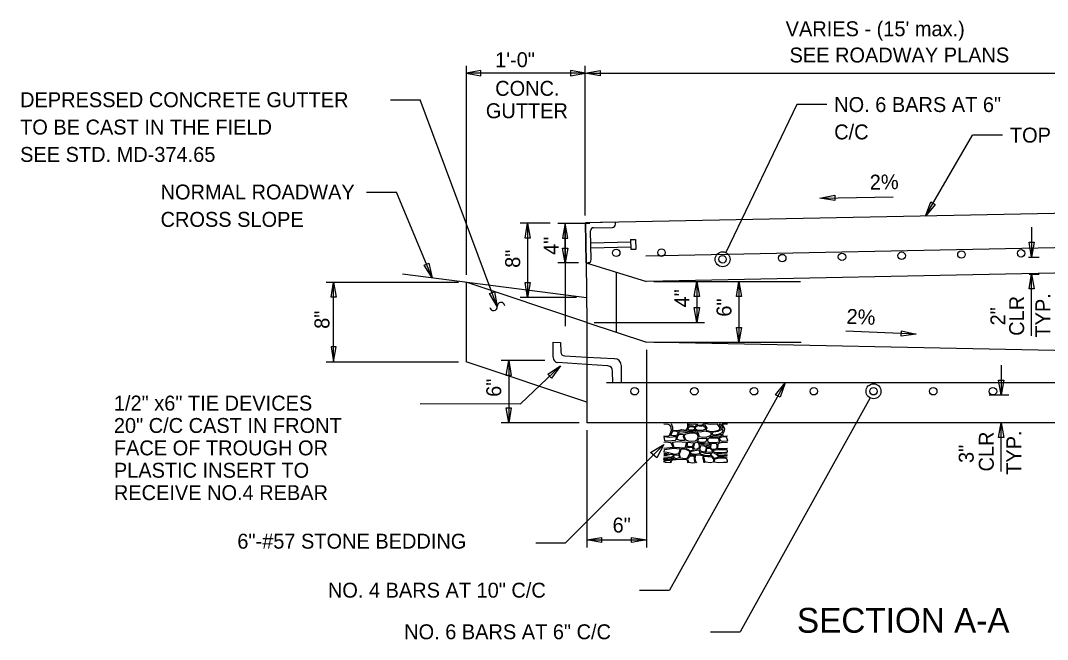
# Model space of a CAD drawing. Extents: x 12.4 to 21.1, y 6 to 16.1.
# Drawn here: x 12.53 to 16.657, y 10.416 to 12.903 of the extents above; entities that cross this region are included whole.
import ezdxf

# ---------------------------------------------------------------- set-up
doc = ezdxf.new("R2010")
doc.units = 0
for name, color, linetype in [('V7_LEVEL_1', 7, 'Continuous'), ('V7_LEVEL_10', 7, 'Continuous'), ('V7_LEVEL_12', 7, 'Continuous')]:
    doc.layers.add(name, color=color, linetype=linetype)

msp = doc.modelspace()

# ---------------------------------------------------------------- linework, layer by layer
at = {"layer": 'V7_LEVEL_1'}
for p, q in [((17.5204, 12.1444), (14.8004, 12.09)), ((14.9204, 12.0924), (14.8004, 12.09)), ((14.9205, 12.0844), (14.9204, 12.0924)), ((14.8036, 11.93), (14.8004, 12.09)), ((14.8004, 12.09), (14.8036, 11.93)), ((14.8004, 12.09), (14.8036, 11.93)), ((14.8233, 11.9424), (14.821, 12.0584)), ((14.8328, 12.0706), (14.9088, 12.0721)), ((14.822, 12.0104), (14.982, 12.0136)), ((14.9818, 12.0228), (15.0018, 12.0232)), ((14.9818, 12.0228), (14.9825, 11.9844)), ((15.0018, 12.0232), (15.0025, 11.9848)), ((17.6389, 12.0086), (15.0431, 11.9567)), ((14.8224, 11.9904), (14.9824, 11.9936)), ((14.9825, 11.9844), (15.0025, 11.9848)), ((14.8036, 11.93), (14.8116, 11.9302)), ((14.8036, 11.93), (15.0451, 11.8548)), ((14.8036, 11.93), (14.8052, 11.69)), ((14.9252, 11.65), (14.9251, 11.8922)), ((17.6852, 11.9076), (15.0451, 11.8548)), ((14.8048, 11.7894), (14.0655, 11.8839)), ((14.8052, 11.69), (14.3204, 11.8516)), ((14.3204, 11.8516), (14.3204, 11.5316)), ((14.8052, 11.69), (14.8052, 11.2868)), ((14.8052, 11.69), (15.0452, 11.61)), ((14.6699, 11.5507), (14.6705, 11.6112)), ((14.6705, 11.6112), (14.7003, 11.6099)), ((14.7003, 11.6099), (14.7008, 11.5717)), ((17.5252, 11.5604), (15.0452, 11.61)), ((14.7175, 11.5552), (14.8053, 11.5504)), ((14.8052, 11.37), (14.3204, 11.5316)), ((14.8053, 11.5207), (14.6893, 11.5284)), ((14.8053, 11.5504), (14.9161, 11.5444)), ((14.8887, 11.5161), (14.8053, 11.5205)), ((14.9436, 11.5188), (14.9441, 11.447)), ((14.9105, 11.4465), (14.9095, 11.4936)), ((17.3791, 11.4467), (14.8852, 11.4467)), ((14.9441, 11.447), (14.9104, 11.4468)), ((17.2852, 11.2868), (14.8052, 11.2868))]:
    msp.add_line(p, q, dxfattribs=at)
for centre in [(14.9241, 11.9698), (15.1059, 11.9706), (15.8311, 11.9534), (16.071, 11.9582), (16.311, 11.963), (16.5509, 11.9678), (15.3512, 11.9438), (15.5911, 11.9486), (14.9978, 11.4133), (15.2378, 11.4133), (15.4778, 11.4133), (15.7178, 11.4133), (15.9578, 11.4133), (16.1978, 11.4133), (16.4378, 11.4133)]:
    msp.add_circle(centre, 0.015, dxfattribs=at)
for centre, radius, start, end in [((14.833, 12.0586), 0.012, 91.1458, 181.1458), ((14.9085, 12.0841), 0.012, 271.1458, 1.1458), ((14.8113, 11.9422), 0.012, 271.1458, 1.1458), ((14.7174, 11.5718), 0.0166, 180.2549, 269.9363), ((14.6904, 11.5484), 0.02, 177.1964, 266.8777), ((14.8894, 11.4952), 0.02, 356.8804, 86.869), ((14.9182, 11.5189), 0.0251, 2.024, 91.7054)]:
    msp.add_arc(centre, radius, start, end, dxfattribs=at)
at = {"layer": 'V7_LEVEL_10'}
for p, q in [((14.3204, 12.7218), (14.3204, 11.8816)), ((14.7989, 12.12), (14.7989, 12.7218)), ((14.7989, 12.12), (14.7989, 12.7218)), ((14.3804, 12.7023), (14.3204, 12.6918)), ((14.8004, 12.6918), (14.3204, 12.6918)), ((14.3204, 12.6918), (14.3804, 12.6813)), ((14.3804, 12.6813), (14.3804, 12.7023)), ((14.8004, 12.6918), (14.7404, 12.7023)), ((14.7404, 12.7023), (14.7404, 12.6813)), ((14.7404, 12.6813), (14.8004, 12.6918)), ((14.7989, 12.6918), (14.8589, 12.7023)), ((14.7989, 12.6918), (17.5204, 12.6918)), ((14.8589, 12.6813), (14.7989, 12.6918)), ((14.8589, 12.7023), (14.8589, 12.6813)), ((14.0163, 12.5853), (14.1363, 12.5853)), ((14.4461, 11.7537), (14.1363, 12.5853)), ((15.6499, 12.5658), (15.3641, 11.9708)), ((15.7699, 12.5658), (15.6499, 12.5658)), ((16.1664, 12.1173), (16.356, 12.443)), ((16.4759, 12.443), (16.3559, 12.443)), ((13.9211, 12.2141), (14.0411, 12.2141)), ((14.1844, 11.8687), (14.0411, 12.2141)), ((15.7426, 12.1894), (16.0371, 12.1953)), ((14.6579, 12.0892), (14.5379, 12.0892)), ((14.5679, 12.0892), (14.5679, 11.7906)), ((14.689, 12.0892), (14.8173, 12.0892)), ((14.719, 12.0892), (14.7085, 12.0292)), ((14.719, 11.929), (14.719, 12.0892)), ((14.7295, 12.0292), (14.719, 12.0892)), ((14.719, 12.0892), (14.719, 11.6744)), ((16.5933, 12.0728), (16.5933, 11.9528)), ((14.7085, 12.0292), (14.7295, 12.0292)), ((14.719, 11.929), (14.7085, 11.989)), ((14.7085, 11.989), (14.7295, 11.989)), ((14.7295, 11.989), (14.719, 11.929)), ((14.7729, 11.929), (14.689, 11.929)), ((16.5809, 11.9528), (16.6233, 11.9528)), ((13.7584, 11.8516), (14.2904, 11.8516)), ((13.7779, 11.7916), (13.7884, 11.8516)), ((13.7884, 11.5316), (13.7884, 11.8516)), ((13.7884, 11.8516), (13.7989, 11.7916)), ((15.0751, 11.8548), (15.278, 11.8548)), ((15.0751, 11.8548), (15.6647, 11.8548)), ((15.248, 11.8548), (15.248, 11.69)), ((15.4172, 11.8548), (15.4172, 11.61)), ((16.5836, 11.8844), (16.6233, 11.8844)), ((16.5933, 11.6361), (16.5933, 11.8844)), ((13.7989, 11.7916), (13.7779, 11.7916)), ((14.7646, 11.7906), (14.5379, 11.7906)), ((14.8352, 11.69), (15.278, 11.69)), ((16.1292, 11.6432), (15.8472, 11.6548)), ((15.0752, 11.61), (15.6667, 11.61)), ((13.7989, 11.5916), (13.7779, 11.5916)), ((13.7779, 11.5916), (13.7884, 11.5316)), ((13.7884, 11.5316), (13.7989, 11.5916)), ((15.0452, 11.58), (15.0452, 10.7854)), ((13.7584, 11.5316), (14.2904, 11.5316)), ((14.6365, 11.5372), (14.4619, 11.5372)), ((14.4919, 11.5372), (14.4919, 11.2868)), ((14.7002, 11.5153), (14.5394, 11.3621)), ((16.4711, 11.5183), (16.4711, 11.3983)), ((15.6023, 11.4467), (15.1379, 10.6138)), ((16.4229, 11.3983), (16.5011, 11.3983)), ((14.1366, 11.3637), (14.5394, 11.3621)), ((15.944, 11.3867), (15.4226, 10.4465)), ((14.7752, 11.2868), (14.4619, 11.2868)), ((15.1148, 11.2835), (15.1148, 11.2835)), ((16.4628, 11.2868), (16.4411, 11.2868)), ((16.4711, 11.0907), (16.4711, 11.2868)), ((14.8052, 11.2568), (14.8052, 10.7854)), ((15.1158, 11.1993), (14.7206, 10.8045)), ((15.1148, 11.126), (15.1148, 11.126)), ((14.8052, 10.8154), (15.0452, 10.8154)), ((14.6006, 10.8045), (14.7206, 10.8045)), ((15.0179, 10.6138), (15.1379, 10.6138)), ((15.3026, 10.4465), (15.4226, 10.4465))]:
    msp.add_line(p, q, dxfattribs=at)
for points in [[(15.8028, 12.1801), (15.7426, 12.1894), (15.8024, 12.2011)], [(16.2057, 12.1639), (16.1664, 12.1173), (16.1875, 12.1744)], [(14.5574, 12.0292), (14.5679, 12.0892), (14.5784, 12.0292)], [(16.6038, 12.0128), (16.5933, 11.9528), (16.5828, 12.0128)], [(14.1711, 11.9281), (14.1844, 11.8687), (14.1518, 11.9201)], [(14.5784, 11.8506), (14.5679, 11.7906), (14.5574, 11.8506)], [(15.2375, 11.7948), (15.248, 11.8548), (15.2585, 11.7948)], [(15.4067, 11.7948), (15.4172, 11.8548), (15.4277, 11.7948)], [(16.5828, 11.8244), (16.5933, 11.8844), (16.6038, 11.8244)], [(14.435, 11.8135), (14.4461, 11.7537), (14.4153, 11.8062)], [(15.2585, 11.75), (15.248, 11.69), (15.2375, 11.75)], [(15.4277, 11.67), (15.4172, 11.61), (15.4067, 11.67)], [(16.0697, 11.6562), (16.1292, 11.6432), (16.0689, 11.6352)], [(14.4814, 11.4772), (14.4919, 11.5372), (14.5024, 11.4772)], [(14.6495, 11.4815), (14.7002, 11.5153), (14.664, 11.4663)], [(15.564, 11.3994), (15.6023, 11.4467), (15.5823, 11.3892)], [(16.4816, 11.4583), (16.4711, 11.3983), (16.4606, 11.4583)], [(14.5024, 11.3468), (14.4919, 11.2868), (14.4814, 11.3468)], [(15.212, 11.2592), (15.2158, 11.2683), (15.2234, 11.272), (15.2384, 11.2687), (15.2386, 11.2596), (15.2296, 11.2571), (15.2213, 11.2574)], [(15.2168, 11.2822), (15.228, 11.281), (15.2434, 11.2827), (15.2458, 11.2787), (15.2439, 11.2744), (15.2394, 11.2709), (15.2334, 11.2732), (15.2242, 11.2746), (15.2163, 11.2732)], [(15.2507, 11.2753), (15.2655, 11.2732), (15.2739, 11.2761), (15.2834, 11.2663), (15.2796, 11.2591), (15.2696, 11.2554), (15.2512, 11.2558), (15.2421, 11.2615), (15.2431, 11.2693)], [(15.2801, 11.282), (15.2789, 11.2779), (15.2884, 11.2659), (15.2839, 11.2573), (15.298, 11.253), (15.3115, 11.2519), (15.3318, 11.256), (15.3404, 11.2609), (15.3397, 11.2681), (15.3306, 11.2808), (15.3044, 11.2798)], [(15.338, 11.2804), (15.3449, 11.2677), (15.3454, 11.2611), (15.3526, 11.262), (15.354, 11.2648), (15.3452, 11.2802)], [(16.4606, 11.2268), (16.4711, 11.2868), (16.4816, 11.2268)], [(15.1163, 11.2308), (15.1367, 11.2292), (15.1643, 11.2308), (15.1638, 11.2183), (15.1605, 11.2156), (15.1344, 11.2125), (15.1187, 11.214)], [(15.1439, 11.2353), (15.1515, 11.2539), (15.1645, 11.2537), (15.1712, 11.2506), (15.1721, 11.243), (15.1657, 11.2347), (15.1529, 11.2339)], [(15.1683, 11.2199), (15.1705, 11.2308), (15.1783, 11.2409), (15.1937, 11.2393), (15.1933, 11.2304), (15.199, 11.2173), (15.1964, 11.2152), (15.1809, 11.2152)], [(15.1757, 11.2448), (15.1785, 11.2532), (15.2054, 11.2537), (15.2149, 11.2547), (15.2206, 11.2536), (15.2206, 11.2489), (15.1999, 11.2456), (15.1816, 11.2434)], [(15.1994, 11.2401), (15.2042, 11.2426), (15.2242, 11.2462), (15.2417, 11.2462), (15.2479, 11.2428), (15.25, 11.2388), (15.2524, 11.2279), (15.2481, 11.2171), (15.241, 11.2125), (15.2258, 11.2109), (15.2142, 11.2121), (15.2044, 11.2164), (15.1978, 11.2288)], [(15.2256, 11.2539), (15.2417, 11.2571), (15.2455, 11.2536), (15.2422, 11.2491), (15.2265, 11.2491)], [(15.2522, 11.2517), (15.2624, 11.2507), (15.2796, 11.254), (15.3027, 11.2482), (15.3061, 11.239), (15.302, 11.2343), (15.2872, 11.2282), (15.2712, 11.2276), (15.2591, 11.2298), (15.2553, 11.2403), (15.2472, 11.2478)], [(15.2572, 11.2247), (15.2722, 11.2233), (15.2872, 11.2241), (15.2867, 11.2171), (15.2841, 11.2103), (15.2736, 11.2075), (15.2598, 11.2087), (15.251, 11.2118)], [(15.2934, 11.2237), (15.2908, 11.2167), (15.2915, 11.2106), (15.3025, 11.2079), (15.3216, 11.2075), (15.3383, 11.2106), (15.3375, 11.2173), (15.333, 11.2249), (15.3118, 11.2243)], [(15.2989, 11.2292), (15.3132, 11.2343), (15.3273, 11.2359), (15.3457, 11.2405), (15.3461, 11.2335), (15.3397, 11.2298), (15.3156, 11.2276)], [(15.3084, 11.2476), (15.3111, 11.2398), (15.3189, 11.2376), (15.3385, 11.2423), (15.349, 11.2472), (15.3535, 11.2575), (15.3461, 11.2581), (15.3316, 11.2515)], [(15.3385, 11.2261), (15.3483, 11.2302), (15.3626, 11.2308), (15.3652, 11.2302), (15.3709, 11.2169), (15.3681, 11.213), (15.3509, 11.212), (15.3433, 11.2138)], [(15.0613, 11.1667), (15.1158, 11.1993), (15.0869, 11.1457)], [(15.1169, 11.1682), (15.1177, 11.1798), (15.1557, 11.1844), (15.1795, 11.1823), (15.1795, 11.176), (15.174, 11.1614), (15.1582, 11.1587), (15.1507, 11.1623), (15.1285, 11.1666)], [(15.1496, 11.2087), (15.1718, 11.2116), (15.2045, 11.2087), (15.2036, 11.1969), (15.2, 11.1846), (15.1573, 11.1873)], [(15.2075, 11.1889), (15.2045, 11.1835), (15.2222, 11.1741), (15.235, 11.1775), (15.23, 11.1878), (15.2172, 11.1862)], [(15.2111, 11.2082), (15.2352, 11.2064), (15.2297, 11.1905), (15.2175, 11.1896), (15.2089, 11.1921)], [(15.24, 11.1789), (15.235, 11.1889), (15.24, 11.2064), (15.2461, 11.2087), (15.2541, 11.2057), (15.2572, 11.1925), (15.2563, 11.1844), (15.2494, 11.18)], [(15.2585, 11.2053), (15.2787, 11.2042), (15.2914, 11.2065), (15.302, 11.2036), (15.3015, 11.1997), (15.2964, 11.1978), (15.2833, 11.1963), (15.2592, 11.2009)], [(15.2621, 11.1726), (15.2594, 11.1814), (15.263, 11.1898), (15.2621, 11.1955), (15.2768, 11.1944), (15.2832, 11.1916), (15.2854, 11.1857), (15.2827, 11.1737), (15.2785, 11.1689)], [(15.2886, 11.1845), (15.3002, 11.1852), (15.3111, 11.1738), (15.3108, 11.1696), (15.2992, 11.1673), (15.2835, 11.1678), (15.2871, 11.175)], [(15.2863, 11.1939), (15.3002, 11.1953), (15.2999, 11.1878), (15.2886, 11.187)], [(15.3101, 11.1796), (15.3037, 11.1852), (15.3037, 11.1945), (15.3063, 11.2028), (15.3154, 11.205), (15.3275, 11.2038), (15.3285, 11.1914), (15.3267, 11.182), (15.3159, 11.1791)], [(15.1157, 11.1435), (15.1468, 11.1457), (15.154, 11.1423), (15.1393, 11.1382), (15.1174, 11.1373), (15.1157, 11.1389)], [(15.1751, 11.1576), (15.177, 11.1478), (15.1745, 11.1439), (15.1629, 11.1421), (15.1565, 11.1451), (15.1537, 11.1485), (15.1576, 11.1562)], [(15.1817, 11.1444), (15.1784, 11.1614), (15.1837, 11.1757), (15.1848, 11.1825), (15.1998, 11.1814), (15.2172, 11.1737), (15.2194, 11.1639), (15.2084, 11.1444), (15.2009, 11.1417)], [(15.2156, 11.1278), (15.2294, 11.1255), (15.2411, 11.1271), (15.238, 11.1378), (15.2391, 11.1476), (15.2366, 11.1507), (15.2311, 11.1519), (15.2194, 11.1516), (15.2114, 11.143), (15.2108, 11.1387)], [(15.2225, 11.1612), (15.2411, 11.156), (15.2397, 11.1537), (15.225, 11.1546), (15.2197, 11.1557)], [(15.2228, 11.1716), (15.2397, 11.1757), (15.256, 11.1775), (15.2588, 11.1696), (15.2566, 11.1616), (15.2425, 11.1587), (15.2269, 11.1621), (15.2217, 11.1678)], [(15.262, 11.1694), (15.2822, 11.1644), (15.3015, 11.1634), (15.3035, 11.1582), (15.3007, 11.1539), (15.285, 11.1539), (15.26, 11.1615)], [(15.2774, 11.1528), (15.2916, 11.1508), (15.3073, 11.1503), (15.3154, 11.1398), (15.3144, 11.1276), (15.3025, 11.1259), (15.2825, 11.1276), (15.279, 11.1348), (15.279, 11.1402), (15.2762, 11.1452)], [(15.3058, 11.1642), (15.3141, 11.1669), (15.3255, 11.1609), (15.3333, 11.153), (15.3351, 11.1481), (15.3187, 11.1435), (15.3128, 11.1495), (15.3065, 11.1543)], [(15.3151, 11.1767), (15.3318, 11.1794), (15.3518, 11.1798), (15.3685, 11.1791), (15.37, 11.174), (15.3695, 11.1688), (15.3629, 11.1665), (15.3455, 11.1653), (15.3252, 11.1661), (15.3184, 11.1675), (15.3149, 11.1731)], [(15.3182, 11.1276), (15.3202, 11.1412), (15.3391, 11.1458), (15.3578, 11.1454), (15.3675, 11.1431), (15.3692, 11.135), (15.37, 11.1305), (15.3667, 11.1274), (15.3548, 11.1263), (15.3341, 11.1261)], [(15.1157, 11.1342), (15.141, 11.1357), (15.1426, 11.1321), (15.1404, 11.126), (15.1218, 11.1267), (15.1163, 11.1292)], [(14.8652, 10.8049), (14.8052, 10.8154), (14.8652, 10.8259)], [(14.9852, 10.8259), (15.0452, 10.8154), (14.9852, 10.8049)]]:
    msp.add_lwpolyline(points, close=True, dxfattribs=at)
for points in [[(15.1148, 11.234), (15.1329, 11.2333), (15.1396, 11.2388), (15.146, 11.2569), (15.1436, 11.272), (15.1398, 11.2773), (15.1322, 11.2792), (15.1148, 11.2805)], [(15.1442, 11.2835), (15.1503, 11.2695), (15.1505, 11.2572), (15.1724, 11.2561), (15.1864, 11.2592), (15.2049, 11.2574), (15.2111, 11.2672), (15.2123, 11.2752), (15.2117, 11.2835)], [(15.2485, 11.2835), (15.2512, 11.2783), (15.2655, 11.2765), (15.2739, 11.2796), (15.2764, 11.2835)], [(15.3706, 11.2805), (15.3607, 11.2814), (15.3497, 11.2804), (15.3585, 11.2632), (15.3573, 11.2527), (15.3504, 11.2396), (15.3504, 11.2357), (15.3588, 11.2329), (15.3706, 11.234)], [(15.1149, 11.2089), (15.1227, 11.2094), (15.1437, 11.2075), (15.1523, 11.1873), (15.1149, 11.183)], [(15.3706, 11.183), (15.3556, 11.1825), (15.3323, 11.1823), (15.3333, 11.2013), (15.3359, 11.205), (15.346, 11.2079), (15.3706, 11.2089)], [(15.1148, 11.164), (15.1274, 11.1632), (15.1329, 11.1623), (15.1338, 11.1607), (15.1268, 11.1589), (15.1149, 11.1579)], [(15.1148, 11.1556), (15.1274, 11.1564), (15.144, 11.1605), (15.1526, 11.1582), (15.1523, 11.1507), (15.1446, 11.1482), (15.1148, 11.1471)], [(15.2483, 11.1259), (15.2438, 11.1314), (15.2416, 11.1426), (15.2436, 11.156), (15.2608, 11.158), (15.2735, 11.1541), (15.2716, 11.1442), (15.2764, 11.126)], [(15.3704, 11.164), (15.3485, 11.1628), (15.328, 11.1634), (15.3336, 11.1582), (15.3467, 11.1568), (15.3581, 11.1572), (15.3706, 11.1579)], [(15.3704, 11.1471), (15.3571, 11.1479), (15.3404, 11.1483), (15.3374, 11.1514), (15.3361, 11.1551), (15.3556, 11.1543), (15.3704, 11.1556)], [(15.1442, 11.126), (15.1457, 11.1348), (15.1498, 11.138), (15.1562, 11.1394), (15.1651, 11.1385), (15.1928, 11.1407), (15.207, 11.1387), (15.2117, 11.126)]]:
    msp.add_lwpolyline(points, dxfattribs=at)
for centre in [(15.3512, 11.9438), (15.9578, 11.4133)]:
    msp.add_circle(centre, 0.03, dxfattribs=at)
for centre, start, end in [((14.461, 11.7551), 8.3056, 185.3613), ((14.4311, 11.7523), 188.3056, 5.3613)]:
    msp.add_arc(centre, 0.015, start, end, dxfattribs=at)

# ---------------------------------------------------------------- texts
at = {"layer": 'V7_LEVEL_12'}
for s, height, p in [("VARIES - (15' max.)", 0.06, (15.6048, 12.8403)), (' SEE ROADWAY PLANS', 0.06, (15.5981, 12.7349)), ('1\'-0"', 0.06, (14.4373, 12.716)), ('CONC.', 0.06, (14.4376, 12.6009)), ('DEPRESSED CONCRETE GUTTER', 0.06, (12.5285, 12.5552)), ('NO. 6 BARS AT 6"', 0.06, (15.7998, 12.5357)), ('GUTTER', 0.06, (14.3999, 12.5109)), ('TO BE CAST IN THE FIELD', 0.06, (12.5285, 12.4452)), ('C/C', 0.06, (15.7998, 12.4257)), ('TOP SLAB', 0.06, (16.5058, 12.4129)), ('SEE STD. MD-374.65', 0.06, (12.5285, 12.3352)), ('NORMAL ROADWAY', 0.06, (13.093, 12.1842)), ('CROSS SLOPE', 0.06, (13.093, 12.0742)), ('1/2" x6" TIE DEVICES', 0.06, (12.9053, 11.3357)), ('20" C/C CAST IN FRONT', 0.06, (12.9053, 11.2457)), ('FACE OF TROUGH OR', 0.06, (12.9053, 11.1557)), ('PLASTIC INSERT TO', 0.06, (12.9053, 11.0657)), ('RECEIVE NO.4 REBAR', 0.06, (12.9053, 10.9757)), ('6"', 0.06, (14.9093, 10.8454)), ('6"-#57 STONE BEDDING', 0.06, (13.4014, 10.7806)), ('NO. 4 BARS AT 10" C/C', 0.06, (13.7653, 10.5837)), ('SECTION A-A', 0.1, (15.65, 10.4426)), ('NO. 6 BARS AT 6" C/C', 0.06, (14.0718, 10.4164))]:
    msp.add_text(s, height=height, dxfattribs=at).set_placement(p)
for s, rotation, p in [('2%', 1.1458, (15.9433, 12.2234)), ('4"', 90, (14.6924, 11.9613)), ('8"', 90, (14.5378, 11.9094)), ('4"', 90, (15.2178, 11.7502)), ('6"', 90, (15.387, 11.7132)), ('CLR', 90, (16.563, 11.6361)), ('TYP.', 90, (16.6683, 11.6291)), ('8"', 90, (13.7714, 11.6642)), ('2%', 357.6557, (15.8483, 11.6847)), ('2"', 90, (16.4878, 11.6779)), ('6"', 90, (14.4618, 11.3909)), ('CLR', 90, (16.441, 11.0907)), ('TYP.', 90, (16.5513, 11.0774)), ('3"', 90, (16.3603, 11.1249))]:
    msp.add_text(s, height=0.06, rotation=rotation, dxfattribs=at).set_placement(p)

doc.saveas('drawing.dxf')
